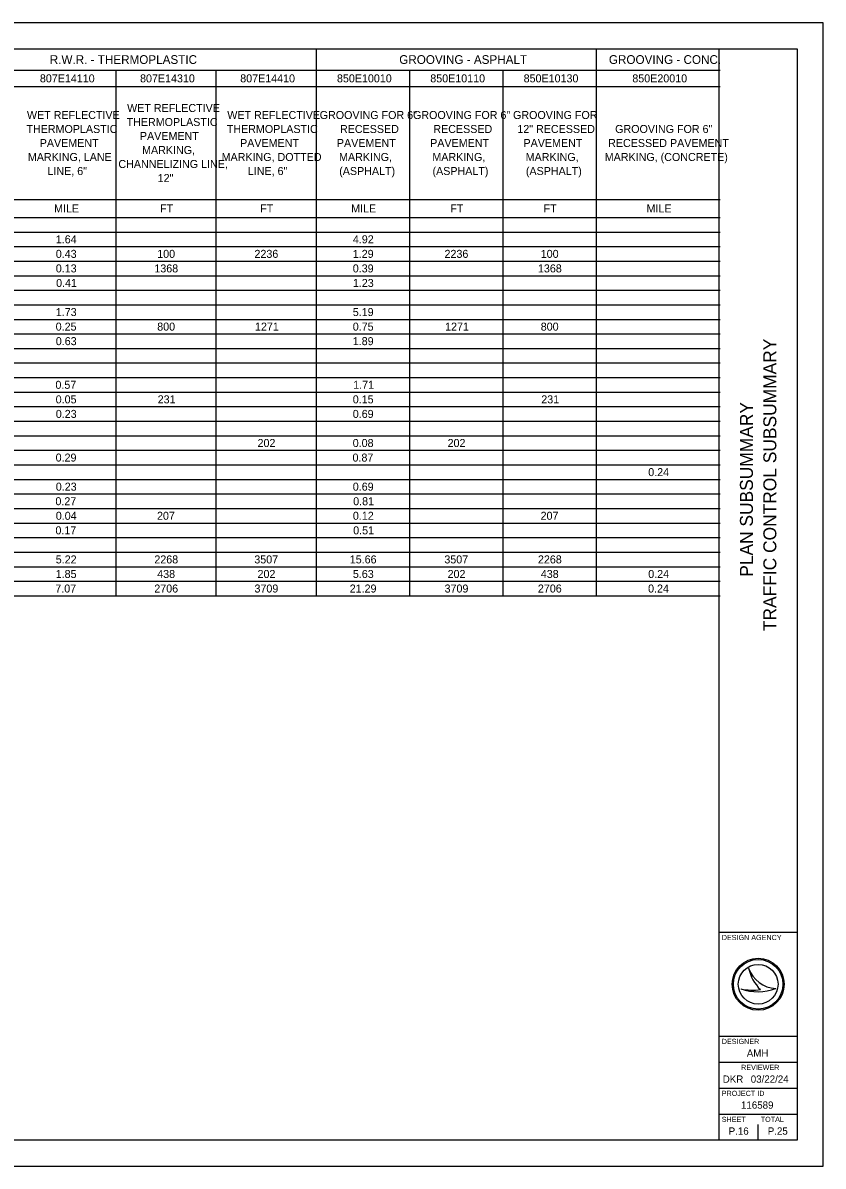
# Model space of a CAD drawing. Extents: x 0 to 34, y 0 to 22.
# Drawn here: x 18.61 to 34, y 0 to 22 of the extents above; entities that cross this region are included whole.
import ezdxf

# ---------------------------------------------------------------- set-up
doc = ezdxf.new("R2010")
doc.units = 0
for name, color, linetype in [('Default', 7, 'Continuous'), ('SH_Border', 7, 'Continuous'), ('SH_Cut_Line', 7, 'Continuous'), ('SH_Data', 7, 'Continuous')]:
    doc.layers.add(name, color=color, linetype=linetype)

msp = doc.modelspace()

# ---------------------------------------------------------------- linework, layer by layer
at = {"layer": 'Default'}
for p, q in [((1.5, 21.5), (32.02, 21.5)), ((24.246, 21.5), (24.246, 10.975)), ((29.632, 21.5), (29.632, 10.975)), ((1.5, 21.088), (32.02, 21.088)), ((20.392, 21.088), (20.392, 10.975)), ((22.319, 21.088), (22.319, 10.975)), ((26.041, 21.088), (26.041, 10.975)), ((27.836, 21.088), (27.836, 10.975)), ((7.858, 20.775), (32.02, 20.775)), ((5.848, 18.601), (32.02, 18.601)), ((1.5, 18.255), (32.02, 18.255)), ((1.5, 17.975), (32.02, 17.975)), ((1.5, 17.695), (32.02, 17.695)), ((1.5, 17.415), (32.02, 17.415)), ((1.5, 17.135), (32.02, 17.135)), ((1.5, 16.855), (32.02, 16.855)), ((1.5, 16.575), (32.02, 16.575)), ((1.5, 16.295), (32.02, 16.295)), ((1.5, 16.015), (32.02, 16.015)), ((1.5, 15.735), (32.02, 15.735)), ((1.5, 15.455), (32.02, 15.455)), ((1.5, 15.175), (32.02, 15.175)), ((1.5, 14.895), (32.02, 14.895)), ((1.5, 14.615), (32.02, 14.615)), ((1.5, 14.335), (32.02, 14.335)), ((1.5, 14.055), (32.02, 14.055)), ((1.5, 13.775), (32.02, 13.775)), ((1.5, 13.495), (32.02, 13.495)), ((1.5, 13.215), (32.02, 13.215)), ((1.5, 12.935), (32.02, 12.935)), ((1.5, 12.655), (32.02, 12.655)), ((1.5, 12.375), (32.02, 12.375)), ((1.5, 12.095), (32.02, 12.095)), ((1.5, 11.815), (32.02, 11.815)), ((1.5, 11.535), (32.02, 11.535)), ((1.5, 11.255), (32.02, 11.255)), ((1.5, 10.975), (32.02, 10.975))]:
    msp.add_line(p, q, dxfattribs=at)
at = {"layer": 'SH_Border'}
for p, q in [((32, 0.5), (32, 21.5)), ((32, 4.5), (33.5, 4.5)), ((32, 2.5), (33.5, 2.5)), ((32, 2), (33.5, 2)), ((32, 1.5), (33.5, 1.5)), ((32, 1), (33.5, 1))]:
    msp.add_line(p, q, dxfattribs=at)
msp.add_lwpolyline([(1.5, 21.5), (33.5, 21.5), (33.5, 0.5), (1.5, 0.5)], close=True, dxfattribs=at)
at = {"layer": 'SH_Cut_Line'}
msp.add_lwpolyline([(0, 0), (34, 0), (34, 22), (0, 22)], close=True, dxfattribs=at)
at = {"layer": 'SH_Data'}
for p, q in [((32.567, 3.81), (32.567, 3.81)), ((32.417, 3.41), (32.417, 3.41)), ((32.75, 3.5), (32.75, 3.5)), ((33.087, 3.419), (33.087, 3.419)), ((32.375, 0.675), (32.375, 0.675)), ((32.75, 0.5), (32.75, 0.8))]:
    msp.add_line(p, q, dxfattribs=at)
for radius in [0.5, 0.477, 0.477, 0.382]:
    msp.add_circle((32.75, 3.5), radius, dxfattribs=at)
for centre, radius, start, end in [((33.116, 3.998), 0.58, 198.9257, 198.9319), ((33.347, 3.97), 0.796, 191.6379, 191.6421), ((33.116, 3.998), 0.58, 198.9319, 267.1657), ((33.347, 3.97), 0.796, 191.6421, 226.0947), ((32.739, 4.37), 1.013, 251.4576, 290.0832), ((32.648, 4.654), 1.266, 259.4964, 259.4995), ((32.739, 4.37), 1.013, 251.4527, 251.4576), ((32.648, 4.654), 1.266, 259.4995, 276.6672)]:
    msp.add_arc(centre, radius, start, end, dxfattribs=at)

# ---------------------------------------------------------------- texts
at = {"layer": 'Default'}
for s, height, p in [('R.W.R. - THERMOPLASTIC', 0.168, (19.123, 21.21)), ('GROOVING - ASPHALT', 0.168, (25.846, 21.21)), ('GROOVING - CONC.', 0.168, (29.879, 21.21)), ('807E14110', 0.154, (18.933, 20.855)), ('807E14310', 0.154, (20.86, 20.855)), ('807E14410', 0.154, (22.787, 20.855)), ('850E10010', 0.154, (24.648, 20.855)), ('850E10110', 0.154, (26.443, 20.855)), ('850E10130', 0.154, (28.239, 20.855)), ('850E20010', 0.154, (30.33, 20.855)), ('WET REFLECTIVE ', 0.154, (18.684, 20.15)), ('WET REFLECTIVE ', 0.154, (20.611, 20.285)), ('WET REFLECTIVE ', 0.154, (22.538, 20.15)), ('GROOVING FOR 6" ', 0.154, (24.316, 20.15)), ('GROOVING FOR 6" ', 0.154, (26.111, 20.15)), ('GROOVING FOR ', 0.154, (28.035, 20.15)), ('THERMOPLASTIC ', 0.154, (18.674, 19.881)), ('THERMOPLASTIC ', 0.154, (20.601, 20.015)), ('THERMOPLASTIC ', 0.154, (22.528, 19.881)), ('RECESSED ', 0.154, (24.706, 19.881)), ('RECESSED ', 0.154, (26.502, 19.881)), ('12" RECESSED ', 0.154, (28.118, 19.881)), ('GROOVING FOR 6" ', 0.154, (29.999, 19.881)), ('PAVEMENT ', 0.154, (20.857, 19.746)), ('PAVEMENT ', 0.154, (18.93, 19.611)), ('MARKING, ', 0.154, (20.899, 19.476)), ('PAVEMENT ', 0.154, (22.784, 19.611)), ('PAVEMENT ', 0.154, (24.646, 19.611)), ('PAVEMENT ', 0.154, (26.441, 19.611)), ('PAVEMENT ', 0.154, (28.236, 19.611)), ('RECESSED PAVEMENT ', 0.154, (29.864, 19.611)), ('MARKING, LANE ', 0.154, (18.702, 19.342)), ('CHANNELIZING LINE, ', 0.154, (20.443, 19.207)), ('MARKING, DOTTED ', 0.154, (22.429, 19.342)), ('MARKING, ', 0.154, (24.688, 19.342)), ('MARKING, ', 0.154, (26.483, 19.342)), ('MARKING, ', 0.154, (28.278, 19.342)), ('MARKING, (CONCRETE)', 0.154, (29.799, 19.342)), ('LINE, 6"', 0.154, (19.079, 19.072)), ('LINE, 6"', 0.154, (22.933, 19.072)), ('(ASPHALT)', 0.154, (24.691, 19.072)), ('(ASPHALT)', 0.154, (26.486, 19.072)), ('(ASPHALT)', 0.154, (28.282, 19.072)), ('12"', 0.154, (21.199, 18.937)), ('MILE', 0.154, (19.206, 18.351)), ('FT', 0.154, (21.244, 18.351)), ('FT', 0.154, (23.171, 18.351)), ('MILE', 0.154, (24.921, 18.351)), ('FT', 0.154, (26.828, 18.351)), ('FT', 0.154, (28.623, 18.351)), ('MILE', 0.154, (30.604, 18.351)), ('1.64', 0.154, (19.239, 17.758)), ('4.92', 0.154, (24.954, 17.758)), ('0.43', 0.154, (19.239, 17.478)), ('100', 0.154, (21.19, 17.478)), ('2236', 0.154, (23.061, 17.478)), ('1.29', 0.154, (24.952, 17.478)), ('2236', 0.154, (26.717, 17.478)), ('100', 0.154, (28.568, 17.478)), ('0.13', 0.154, (19.239, 17.198)), ('1368', 0.154, (21.135, 17.198)), ('0.39', 0.154, (24.952, 17.198)), ('1368', 0.154, (28.514, 17.198)), ('0.41', 0.154, (19.245, 16.918)), ('1.23', 0.154, (24.954, 16.918)), ('1.73', 0.154, (19.239, 16.358)), ('5.19', 0.154, (24.952, 16.358)), ('0.25', 0.154, (19.237, 16.078)), ('800', 0.154, (21.19, 16.078)), ('1271', 0.154, (23.071, 16.078)), ('0.75', 0.154, (24.952, 16.078)), ('1271', 0.154, (26.728, 16.078)), ('800', 0.154, (28.568, 16.078)), ('0.63', 0.154, (19.239, 15.798)), ('1.89', 0.154, (24.952, 15.798)), ('0.57', 0.154, (19.232, 14.958)), ('1.71', 0.154, (24.96, 14.958)), ('0.05', 0.154, (19.237, 14.678)), ('231', 0.154, (21.199, 14.678)), ('0.15', 0.154, (24.952, 14.678)), ('231', 0.154, (28.578, 14.678)), ('0.23', 0.154, (19.239, 14.398)), ('0.69', 0.154, (24.952, 14.398)), ('202', 0.154, (23.12, 13.838)), ('0.08', 0.154, (24.951, 13.838)), ('202', 0.154, (26.776, 13.838)), ('0.29', 0.154, (19.236, 13.558)), ('0.87', 0.154, (24.947, 13.558)), ('0.24', 0.154, (30.636, 13.278)), ('0.23', 0.154, (19.239, 12.998)), ('0.69', 0.154, (24.952, 12.998)), ('0.27', 0.154, (19.232, 12.718)), ('0.81', 0.154, (24.96, 12.718)), ('0.04', 0.154, (19.239, 12.438)), ('207', 0.154, (21.186, 12.438)), ('0.12', 0.154, (24.954, 12.438)), ('207', 0.154, (28.565, 12.438)), ('0.17', 0.154, (19.232, 12.158)), ('0.51', 0.154, (24.96, 12.158)), ('5.22', 0.154, (19.238, 11.598)), ('2268', 0.154, (21.135, 11.598)), ('3507', 0.154, (23.058, 11.598)), ('15.66', 0.154, (24.894, 11.598)), ('3507', 0.154, (26.714, 11.598)), ('2268', 0.154, (28.514, 11.598)), ('1.85', 0.154, (19.237, 11.318)), ('438', 0.154, (21.19, 11.318)), ('202', 0.154, (23.12, 11.318)), ('5.63', 0.154, (24.954, 11.318)), ('202', 0.154, (26.776, 11.318)), ('438', 0.154, (28.569, 11.318)), ('0.24', 0.154, (30.636, 11.318)), ('7.07', 0.154, (19.23, 11.038)), ('2706', 0.154, (21.134, 11.038)), ('3709', 0.154, (23.061, 11.038)), ('21.29', 0.154, (24.893, 11.038)), ('3709', 0.154, (26.718, 11.038)), ('2706', 0.154, (28.513, 11.038)), ('0.24', 0.154, (30.633, 11.038))]:
    msp.add_text(s, height=height, dxfattribs=at).set_placement(p)
at = {"layer": 'SH_Data'}
for s, p in [('TRAFFIC CONTROL SUBSUMMARY', (33.1, 10.295)), ('PLAN SUBSUMMARY', (32.65, 11.341))]:
    msp.add_text(s, height=0.25, rotation=90, dxfattribs=at).set_placement(p)
for s, height, p in [('DESIGN AGENCY', 0.1, (32.05, 4.35)), ('DESIGNER', 0.1, (32.05, 2.35)), ('AMH', 0.14, (32.532, 2.105)), ('REVIEWER', 0.1, (32.422, 1.85)), ('DKR', 0.14, (32.069, 1.605)), ('03/22/24', 0.14, (32.608, 1.605)), ('PROJECT ID', 0.1, (32.05, 1.35)), ('116589', 0.14, (32.42, 1.105)), ('SHEET', 0.1, (32.05, 0.85)), ('TOTAL', 0.1, (32.8, 0.85)), ('P.16', 0.14, (32.183, 0.605)), ('P.25', 0.14, (32.935, 0.605))]:
    msp.add_text(s, height=height, dxfattribs=at).set_placement(p)

doc.saveas('drawing.dxf')
